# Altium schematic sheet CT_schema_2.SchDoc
size 298 x 159 mm
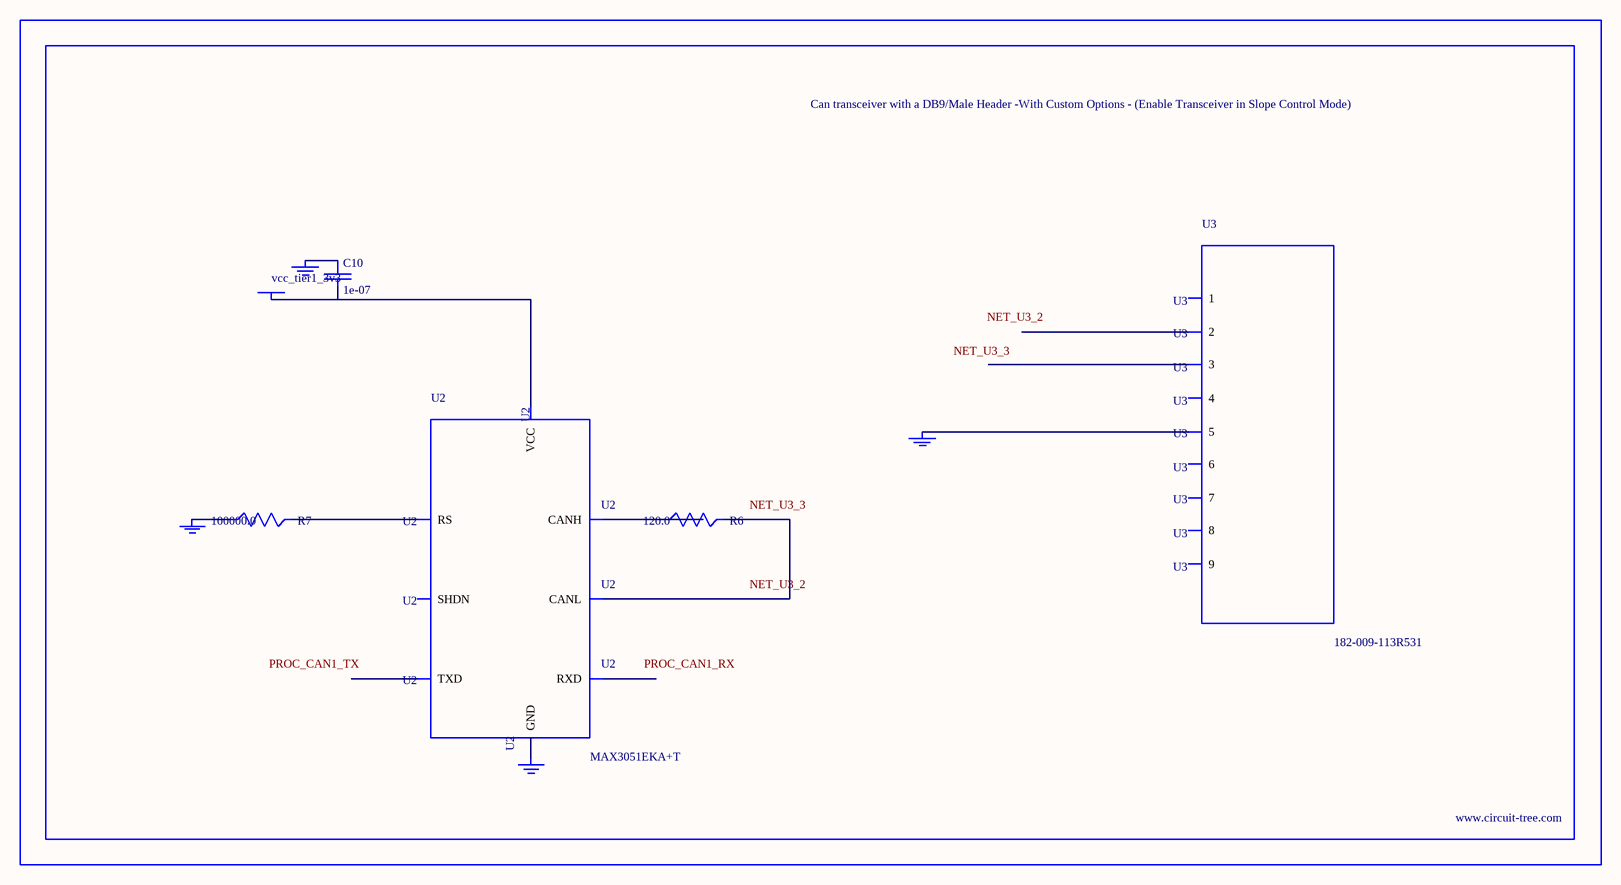
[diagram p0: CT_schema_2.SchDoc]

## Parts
BORDER1  (no value)
C10  1e-07  [C0402]
GND_INSTANCE_1_0  (no value)
GND_INSTANCE_1_1  (no value)
GND_INSTANCE_1_2  (no value)
GND_INSTANCE_1_3  (no value)
POWER_INSTANCE_1_0  vcc_tier1_3v3
R6  120.0  [R0603]
R7  100000.0  [R0603]
U2  MAX3051EKA+T  [SOT-23-8]
U3  182-009-113R531  [182-009-MALE]

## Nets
NetC10_1: C10.1 GND_INSTANCE_1_0.0(GND)
NetC10_2: C10.2 POWER_INSTANCE_1_0.0(PWR) U2.3(VCC)
NetGND_INSTANCE_1_1_0: GND_INSTANCE_1_1.0(GND) R7.1
NetGND_INSTANCE_1_2_0: GND_INSTANCE_1_2.0(GND) U2.2(GND)
NetGND_INSTANCE_1_3_0: GND_INSTANCE_1_3.0(GND) U3.5
NetR6_1: R6.1 U2.7(CANH)
NetR6_2: R6.2 U2.6(CANL)
NetR7_2: R7.2 U2.8(RS)

Not connected (* = marked no-connect by the designer): U2 1(TXD) 4(RXD) 5(SHDN); U3 1 2 3 4 6 7 8 9

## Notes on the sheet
- Labels drawn without touching a wire or pin: NET_U3_2, NET_U3_3, PROC_CAN1_RX, PROC_CAN1_TX

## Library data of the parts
BORDER1 = BORDER_PAGE1
C10 = C0402C104K3RACTU
GND_INSTANCE_1_0-GND_INSTANCE_1_3 = GND
POWER_INSTANCE_1_0 = PWR
R6 = RC0603JR-07120RL
R7 = RC0603JR-07100KL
